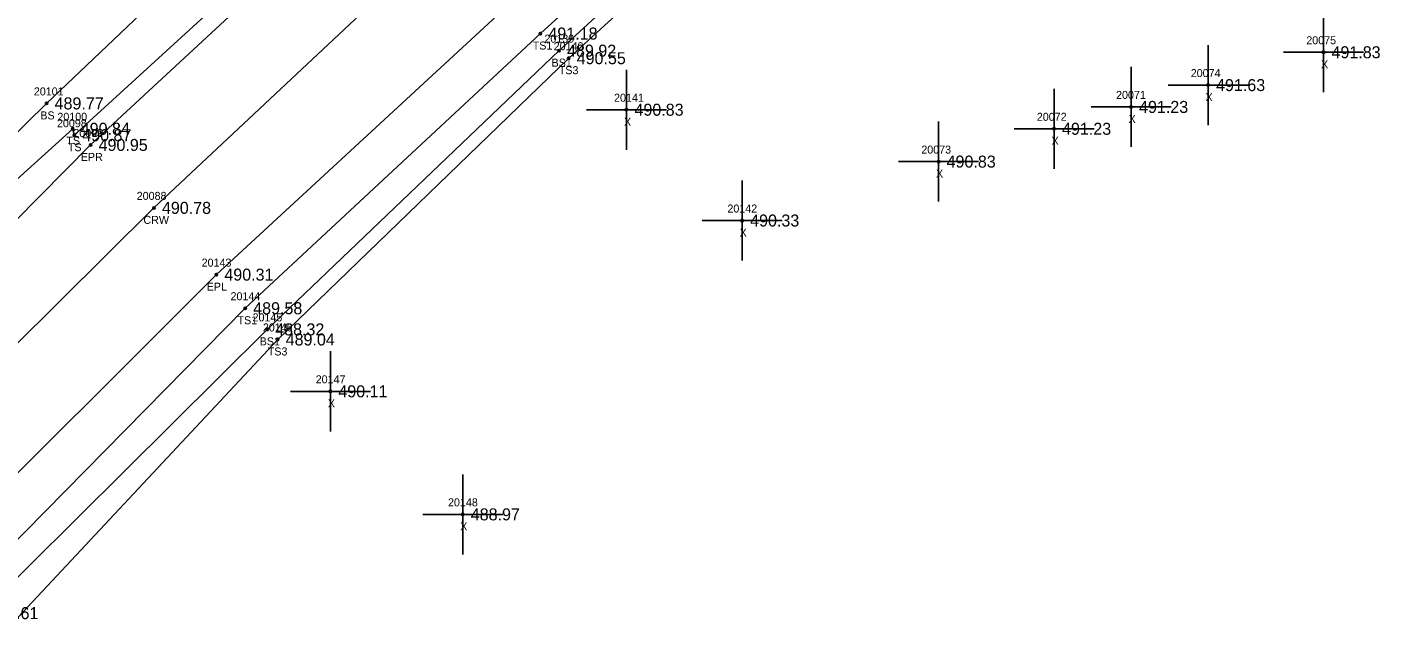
# Model space of a CAD drawing. Extents: x 1741010 to 1742139, y 749382 to 750625.
# Drawn here: x 1741967.6 to 1742136.6, y 750428.2 to 750502.8 of the extents above; entities that cross this region are included whole.
import ezdxf

# ---------------------------------------------------------------- set-up
doc = ezdxf.new("R2010")
doc.units = 0
for name, color, linetype in [('RD_DTM_BkLn1', 7, 'Continuous'), ('RD_DTM_BkLn2', 7, 'Continuous'), ('RD_DTM_BkLn_txCode', 7, 'Continuous'), ('RD_EX_Misc', 7, 'Continuous'), ('RD_EX_Misc_txCode', 7, 'Continuous'), ('RD_EX_Road', 7, 'Continuous'), ('RD_EX_Road_txCode', 7, 'Continuous'), ('RD_EX_TX_Misc_ELEV', 7, 'Continuous'), ('RD_EX_TX_Road_ELEV', 7, 'Continuous'), ('RD_HC_Survey_ELEV', 7, 'Continuous'), ('RD_HC_Survey_txCode', 7, 'Continuous'), ('RD_SMD_Locator', 7, 'Continuous')]:
    doc.layers.add(name, color=color, linetype=linetype)

msp = doc.modelspace()

# ---------------------------------------------------------------- linework, layer by layer
at = {"layer": 'RD_DTM_BkLn1'}
msp.add_lwpolyline([(1742095.1, 750579.47), (1742056.96, 750547.11), (1742019.74, 750514.22), (1741983.45, 750480.17), (1741948.01, 750445.01), (1741913.15, 750409.3), (1741879.03, 750372.99), (1741811.59, 750300.09), (1741743.65, 750226.52), (1741676.29, 750153.06), (1741642.32, 750115.53), (1741610.32, 750077.63)], dxfattribs=at)
at = {"layer": 'RD_DTM_BkLn2'}
for points in [[(1742105.6, 750567.48), (1742094.25, 750560.49), (1742091.64, 750555.7), (1742067.93, 750534.94), (1742031.73, 750501.95), (1741994.85, 750467.63), (1741959.82, 750432.06), (1741925.8, 750396.31), (1741891.25, 750362.62), (1741824.36, 750287.7), (1741756.44, 750214.6), (1741688.69, 750142.04), (1741655.55, 750103.43), (1741644.64, 750083.31), (1741626.06, 750060.3), (1741620, 750055.3), (1741614.97, 750059.12), (1741617.5, 750064.27), (1741619.23, 750067.96)], [(1742107.37, 750564.98), (1742099.21, 750558.66), (1742095.99, 750559.5), (1742095.15, 750554.39), (1742069.73, 750532.61), (1742034.06, 750499.81), (1741997.6, 750464.99), (1741961.88, 750429.54), (1741928.13, 750394.17), (1741895.34, 750359.02), (1741826.5, 750286.36), (1741758.73, 750213.29), (1741690.1, 750140.59), (1741658.36, 750099.77), (1741650.43, 750077.87), (1741632.9, 750061.59), (1741621.97, 750051.56), (1741618.99, 750048.78), (1741611.88, 750047.79)], [(1742108.6, 750563.87), (1742101.48, 750556.48), (1742102.57, 750548.5), (1742101.05, 750532.99), (1742105.06, 750513.92), (1742103.27, 750510.53), (1742100.54, 750509.6), (1742099.13, 750514.58), (1742095.78, 750530.6), (1742094.19, 750550.08), (1742071, 750531.59), (1742035.26, 750498.87), (1741998.91, 750463.73), (1741964.71, 750427.12), (1741930.26, 750392.09), (1741896.36, 750357.96), (1741828.15, 750284.74), (1741760.22, 750211.9), (1741691.37, 750138.81), (1741661.95, 750096.11), (1741655.14, 750072.69), (1741637.21, 750056.01), (1741627.61, 750046.43), (1741623.09, 750045.5)], [(1742037.14, 750559.31), (1742007.02, 750528.39), (1741970.04, 750493.22), (1741934.59, 750458.38), (1741921.36, 750445.71), (1741908.08, 750432.71)], [(1742045.12, 750555.47), (1742011.8, 750524.29), (1741973.5, 750489.25), (1741973.31, 750490.05), (1741936.72, 750456.96), (1741909.62, 750428.48), (1741903.95, 750430.57), (1741885.98, 750437.55), (1741892.83, 750449.28), (1741921.95, 750473.14), (1741959.65, 750503.64), (1742000.15, 750536.41)]]:
    msp.add_lwpolyline(points, dxfattribs=at)
at = {"layer": 'RD_EX_Misc'}
for p, q in [((1742129.55, 750494.61), (1742129.55, 750504.61)), ((1742115.13, 750490.51), (1742115.13, 750500.51)), ((1742124.55, 750499.61), (1742134.55, 750499.61)), ((1742042.48, 750487.43), (1742042.48, 750497.43)), ((1742105.51, 750487.78), (1742105.51, 750497.78)), ((1742095.89, 750485.05), (1742095.89, 750495.05)), ((1742110.13, 750495.51), (1742120.13, 750495.51)), ((1742037.48, 750492.43), (1742047.48, 750492.43)), ((1742100.51, 750492.78), (1742110.51, 750492.78)), ((1742081.47, 750480.95), (1742081.47, 750490.95)), ((1742090.89, 750490.05), (1742100.89, 750490.05)), ((1742076.47, 750485.95), (1742086.47, 750485.95)), ((1742056.93, 750473.59), (1742056.93, 750483.59)), ((1742051.93, 750478.59), (1742061.93, 750478.59)), ((1742005.49, 750452.25), (1742005.49, 750462.25)), ((1742000.49, 750457.25), (1742010.49, 750457.25)), ((1742022.03, 750436.88), (1742022.03, 750446.88)), ((1742017.03, 750441.88), (1742027.03, 750441.88))]:
    msp.add_line(p, q, dxfattribs=at)
at = {"layer": 'RD_EX_Road'}
for points in [[(1742095.24, 750593.27), (1742088.27, 750587.97), (1742078.23, 750580.89), (1742049.13, 750555.21), (1742012.94, 750522.73), (1741975.54, 750488.03), (1741940.71, 750452.82), (1741916.22, 750428.67), (1741904.72, 750416.99), (1741884.38, 750395.02), (1741870.75, 750380.27), (1741817.36, 750322.98), (1741803.89, 750307.66), (1741783.86, 750287.33), (1741735.44, 750234.07), (1741718.84, 750214.98), (1741710.25, 750205.58), (1741668.97, 750159.8), (1741635, 750122.49), (1741604.35, 750087.7), (1741600.63, 750085.47)], [(1742102.43, 750570.61), (1742093.26, 750562.71), (1742064.72, 750538.42), (1742027.92, 750505.65), (1741991.25, 750471.83), (1741956.32, 750436.98), (1741921.43, 750401.39), (1741886.79, 750364.93), (1741819.64, 750292.67), (1741751.78, 750219.01), (1741684.42, 750145.59), (1741650.98, 750108.5), (1741637.17, 750092.42), (1741621.17, 750073.94), (1741621.31, 750072.22), (1741619.24, 750070.27)]]:
    msp.add_lwpolyline(points, dxfattribs=at)
at = {"layer": 'RD_SMD_Locator'}
for centre in [(1742031.73, 750501.95), (1742034.06, 750499.81), (1742129.55, 750499.61), (1742035.26, 750498.87), (1742115.13, 750495.51), (1741970.04, 750493.22), (1742105.51, 750492.78), (1742042.48, 750492.43), (1741973.31, 750490.05), (1742095.89, 750490.05), (1741973.5, 750489.25), (1741975.54, 750488.03), (1742081.47, 750485.95), (1741983.45, 750480.17), (1742056.93, 750478.59), (1741991.25, 750471.83), (1741994.85, 750467.63), (1741997.6, 750464.99), (1741998.91, 750463.73), (1742005.49, 750457.25), (1742022.03, 750441.88)]:
    msp.add_circle(centre, 0.15, dxfattribs=at)

# ---------------------------------------------------------------- texts
at = {"layer": 'RD_DTM_BkLn_txCode'}
for s, p in [('20139', (1742032.23, 750500.81)), ('TS1', (1742030.77, 750499.95)), ('20140', (1742033.39, 750499.87)), ('BS1', (1742033.12, 750497.81)), ('TS3', (1742034.02, 750496.87)), ('20101', (1741968.45, 750494.22)), ('BS', (1741969.26, 750491.22)), ('20098', (1741971.34, 750490.25)), ('20100', (1741971.39, 750491.05)), ('TS', (1741972.51, 750488.05)), ('TS', (1741972.7, 750487.25)), ('20144', (1741993.02, 750468.63)), ('TS1', (1741993.89, 750465.63)), ('20145', (1741995.77, 750465.99)), ('20146', (1741997.06, 750464.73)), ('BS1', (1741996.66, 750462.99)), ('TS3', (1741997.67, 750461.73))]:
    msp.add_text(s, height=1, dxfattribs=at).set_placement(p)
at = {"layer": 'RD_EX_Misc_txCode'}
for s, p in [('20075', (1742127.4, 750500.61)), ('X', (1742129.24, 750497.61)), ('20074', (1742112.97, 750496.51)), ('20071', (1742103.64, 750493.78)), ('20141', (1742040.93, 750493.43)), ('X', (1742114.81, 750493.51)), ('X', (1742042.17, 750490.43)), ('20072', (1742093.74, 750491.05)), ('X', (1742105.2, 750490.78)), ('20073', (1742079.31, 750486.95)), ('X', (1742095.58, 750488.05)), ('X', (1742081.15, 750483.95)), ('20142', (1742055.09, 750479.59)), ('X', (1742056.61, 750476.59)), ('20147', (1742003.66, 750458.25)), ('X', (1742005.18, 750455.25)), ('20148', (1742020.19, 750442.88)), ('X', (1742021.71, 750439.88))]:
    msp.add_text(s, height=1, dxfattribs=at).set_placement(p)
at = {"layer": 'RD_EX_Road_txCode'}
for s, p in [('20099', (1741973.38, 750489.03)), ('EPR', (1741974.31, 750486.03)), ('20143', (1741989.41, 750472.83)), ('EPL', (1741990.04, 750469.83))]:
    msp.add_text(s, height=1, dxfattribs=at).set_placement(p)
at = {"layer": 'RD_EX_TX_Misc_ELEV'}
for s, p in [('491.18', (1742032.73, 750501.2)), ('489.92', (1742035.06, 750499.06)), ('490.55', (1742036.26, 750498.12)), ('491.83', (1742130.55, 750498.86)), ('491.63', (1742116.13, 750494.76)), ('489.77', (1741971.04, 750492.47)), ('490.83', (1742043.48, 750491.68)), ('491.23', (1742106.51, 750492.03)), ('490.84', (1741974.31, 750489.3)), ('490.87', (1741974.5, 750488.5)), ('491.23', (1742096.89, 750489.3)), ('490.83', (1742082.47, 750485.2)), ('490.33', (1742057.93, 750477.84)), ('489.58', (1741995.85, 750466.88)), ('488.32', (1741998.6, 750464.24)), ('489.04', (1741999.91, 750462.98)), ('490.11', (1742006.49, 750456.5)), ('488.97', (1742023.03, 750441.13)), ('485.61', (1741962.88, 750428.79))]:
    msp.add_text(s, height=1.5, dxfattribs=at).set_placement(p)
at = {"layer": 'RD_EX_TX_Road_ELEV'}
for s, p in [('490.95', (1741976.54, 750487.28)), ('490.31', (1741992.25, 750471.08))]:
    msp.add_text(s, height=1.5, dxfattribs=at).set_placement(p)
at = {"layer": 'RD_HC_Survey_ELEV'}
msp.add_text('490.78', height=1.5, dxfattribs=at).set_placement((1741984.45, 750479.42))
at = {"layer": 'RD_HC_Survey_txCode'}
for s, p in [('20088', (1741981.3, 750481.17)), ('CRW', (1741982.14, 750478.17))]:
    msp.add_text(s, height=1, dxfattribs=at).set_placement(p)

doc.saveas('drawing.dxf')
